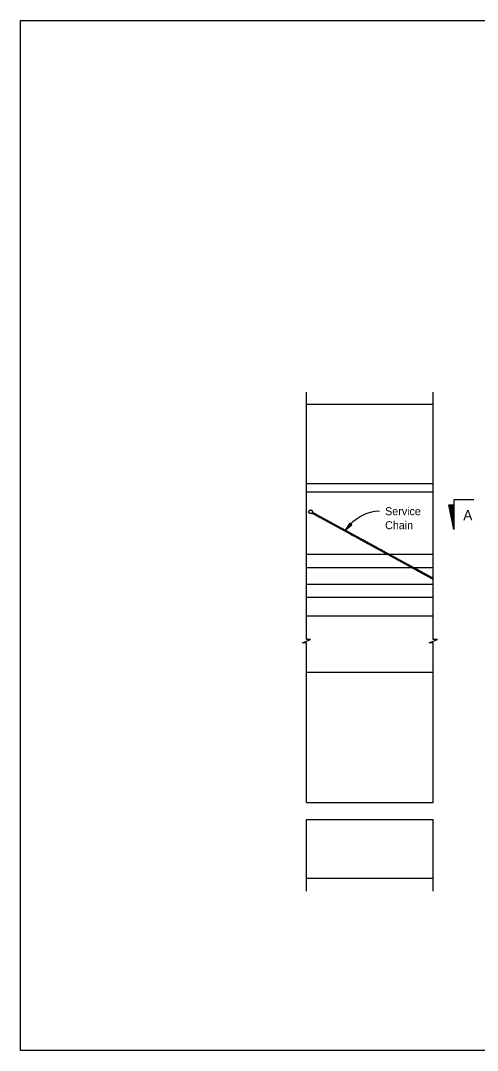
# Model space of a CAD drawing. Extents: x 83976.6 to 84012, y 72958.9 to 72975.6.
# Drawn here: x 83976.59 to 83982.35, y 72960.16 to 72973.13 of the extents above; entities that cross this region are included whole.
import ezdxf

# ---------------------------------------------------------------- set-up
doc = ezdxf.new("R2010")
doc.units = 0
for name, color, linetype in [('DSTitle', 7, 'Continuous'), ('Patterning', 7, 'Continuous'), ('PlotBorder_dp', 7, 'Continuous'), ('RefPtStaTie', 7, 'Continuous'), ('SheetLines_dp', 7, 'Continuous'), ('SupstrConc', 7, 'Continuous')]:
    doc.layers.add(name, color=color, linetype=linetype)

msp = doc.modelspace()

# ---------------------------------------------------------------- linework, layer by layer
at = {"layer": 'DSTitle'}
for radius in [0.0241, 0.0222]:
    msp.add_circle((83980.244, 72966.944), radius, dxfattribs=at)
for centre, major_axis, ratio in [((83980.274, 72966.926), (-0.0135, 0.0073), 0.530594), ((83980.274, 72966.926), (-0.0117, 0.0064), 0.458548), ((83980.298, 72966.914), (-0.0135, 0.0073), 0.530594), ((83980.298, 72966.914), (-0.0117, 0.0064), 0.458548), ((83980.321, 72966.901), (-0.0135, 0.0073), 0.530594), ((83980.321, 72966.901), (-0.0117, 0.0064), 0.458548), ((83980.344, 72966.888), (-0.0135, 0.0073), 0.530594), ((83980.344, 72966.888), (-0.0117, 0.0064), 0.458548), ((83980.368, 72966.875), (-0.0135, 0.0073), 0.530594), ((83980.368, 72966.875), (-0.0117, 0.0064), 0.458548), ((83980.391, 72966.863), (-0.0135, 0.0073), 0.530594), ((83980.391, 72966.863), (-0.0117, 0.0064), 0.458548), ((83980.414, 72966.85), (-0.0135, 0.0073), 0.530594), ((83980.414, 72966.85), (-0.0117, 0.0064), 0.458548), ((83980.438, 72966.837), (-0.0135, 0.0073), 0.530594), ((83980.438, 72966.837), (-0.0117, 0.0064), 0.458548), ((83980.461, 72966.825), (-0.0135, 0.0073), 0.530594), ((83980.461, 72966.825), (-0.0117, 0.0064), 0.458548), ((83980.484, 72966.812), (-0.0135, 0.0073), 0.530594), ((83980.484, 72966.812), (-0.0117, 0.0064), 0.458548), ((83980.508, 72966.799), (-0.0135, 0.0073), 0.530594), ((83980.508, 72966.799), (-0.0117, 0.0064), 0.458548), ((83980.531, 72966.786), (-0.0135, 0.0073), 0.530594), ((83980.531, 72966.786), (-0.0117, 0.0064), 0.458548), ((83980.554, 72966.774), (-0.0135, 0.0073), 0.530594), ((83980.554, 72966.774), (-0.0117, 0.0064), 0.458548), ((83980.578, 72966.761), (-0.0135, 0.0073), 0.530594), ((83980.578, 72966.761), (-0.0117, 0.0064), 0.458548), ((83980.601, 72966.748), (-0.0135, 0.0073), 0.530594), ((83980.601, 72966.748), (-0.0117, 0.0064), 0.458548), ((83980.624, 72966.735), (-0.0135, 0.0073), 0.530594), ((83980.624, 72966.735), (-0.0117, 0.0064), 0.458548), ((83980.648, 72966.723), (-0.0135, 0.0073), 0.530594), ((83980.648, 72966.723), (-0.0117, 0.0064), 0.458548), ((83980.671, 72966.71), (-0.0135, 0.0073), 0.530594), ((83980.671, 72966.71), (-0.0117, 0.0064), 0.458548), ((83980.694, 72966.697), (-0.0135, 0.0073), 0.530594), ((83980.694, 72966.697), (-0.0117, 0.0064), 0.458548), ((83980.718, 72966.685), (-0.0135, 0.0073), 0.530594), ((83980.718, 72966.685), (-0.0117, 0.0064), 0.458548), ((83980.741, 72966.672), (-0.0135, 0.0073), 0.530594), ((83980.741, 72966.672), (-0.0117, 0.0064), 0.458548), ((83980.764, 72966.659), (-0.0135, 0.0073), 0.530594), ((83980.764, 72966.659), (-0.0117, 0.0064), 0.458548), ((83980.788, 72966.646), (-0.0135, 0.0073), 0.530594), ((83980.788, 72966.646), (-0.0117, 0.0064), 0.458548), ((83980.811, 72966.634), (-0.0135, 0.0073), 0.530594), ((83980.811, 72966.634), (-0.0117, 0.0064), 0.458548), ((83980.834, 72966.621), (-0.0135, 0.0073), 0.530594), ((83980.834, 72966.621), (-0.0117, 0.0064), 0.458548), ((83980.857, 72966.608), (-0.0135, 0.0073), 0.530594), ((83980.857, 72966.608), (-0.0117, 0.0064), 0.458548), ((83980.881, 72966.596), (-0.0135, 0.0073), 0.530594), ((83980.881, 72966.596), (-0.0117, 0.0064), 0.458548), ((83980.904, 72966.583), (-0.0135, 0.0073), 0.530594), ((83980.904, 72966.583), (-0.0117, 0.0064), 0.458548), ((83980.927, 72966.57), (-0.0135, 0.0073), 0.530594), ((83980.927, 72966.57), (-0.0117, 0.0064), 0.458548), ((83980.951, 72966.557), (-0.0135, 0.0073), 0.530594), ((83980.951, 72966.557), (-0.0117, 0.0064), 0.458548), ((83980.974, 72966.545), (-0.0135, 0.0073), 0.530594), ((83980.974, 72966.545), (-0.0117, 0.0064), 0.458548), ((83980.997, 72966.532), (-0.0135, 0.0073), 0.530594), ((83980.997, 72966.532), (-0.0117, 0.0064), 0.458548), ((83981.021, 72966.519), (-0.0135, 0.0073), 0.530594), ((83981.021, 72966.519), (-0.0117, 0.0064), 0.458548), ((83981.044, 72966.507), (-0.0135, 0.0073), 0.530594), ((83981.044, 72966.507), (-0.0117, 0.0064), 0.458548), ((83981.067, 72966.494), (-0.0135, 0.0073), 0.530594), ((83981.067, 72966.494), (-0.0117, 0.0064), 0.458548), ((83981.091, 72966.481), (-0.0135, 0.0073), 0.530594), ((83981.091, 72966.481), (-0.0117, 0.0064), 0.458548), ((83981.114, 72966.468), (-0.0135, 0.0073), 0.530594), ((83981.114, 72966.468), (-0.0117, 0.0064), 0.458548), ((83981.137, 72966.456), (-0.0135, 0.0073), 0.530594), ((83981.137, 72966.456), (-0.0117, 0.0064), 0.458548), ((83981.161, 72966.443), (-0.0135, 0.0073), 0.530594), ((83981.161, 72966.443), (-0.0117, 0.0064), 0.458548), ((83981.184, 72966.43), (-0.0135, 0.0073), 0.530594), ((83981.184, 72966.43), (-0.0117, 0.0064), 0.458548), ((83981.207, 72966.417), (-0.0135, 0.0073), 0.530594), ((83981.207, 72966.417), (-0.0117, 0.0064), 0.458548), ((83981.231, 72966.405), (-0.0135, 0.0073), 0.530594), ((83981.231, 72966.405), (-0.0117, 0.0064), 0.458548), ((83981.254, 72966.392), (-0.0135, 0.0073), 0.530594), ((83981.254, 72966.392), (-0.0117, 0.0064), 0.458548), ((83981.277, 72966.379), (-0.0135, 0.0073), 0.530594), ((83981.277, 72966.379), (-0.0117, 0.0064), 0.458548), ((83981.301, 72966.367), (-0.0135, 0.0073), 0.530594), ((83981.301, 72966.367), (-0.0117, 0.0064), 0.458548), ((83981.324, 72966.354), (-0.0135, 0.0073), 0.530594), ((83981.324, 72966.354), (-0.0117, 0.0064), 0.458548), ((83981.347, 72966.341), (-0.0135, 0.0073), 0.530594), ((83981.347, 72966.341), (-0.0117, 0.0064), 0.458548), ((83981.371, 72966.328), (-0.0135, 0.0073), 0.530594), ((83981.371, 72966.328), (-0.0117, 0.0064), 0.458548), ((83981.394, 72966.316), (-0.0135, 0.0073), 0.530594), ((83981.394, 72966.316), (-0.0117, 0.0064), 0.458548), ((83981.417, 72966.303), (-0.0135, 0.0073), 0.530594), ((83981.417, 72966.303), (-0.0117, 0.0064), 0.458548), ((83981.441, 72966.29), (-0.0135, 0.0073), 0.530594), ((83981.441, 72966.29), (-0.0117, 0.0064), 0.458548), ((83981.464, 72966.278), (-0.0135, 0.0073), 0.530594), ((83981.464, 72966.278), (-0.0117, 0.0064), 0.458548), ((83981.487, 72966.265), (-0.0135, 0.0073), 0.530594), ((83981.487, 72966.265), (-0.0117, 0.0064), 0.458548), ((83981.511, 72966.252), (-0.0135, 0.0073), 0.530594), ((83981.511, 72966.252), (-0.0117, 0.0064), 0.458548), ((83981.534, 72966.239), (-0.0135, 0.0073), 0.530594), ((83981.534, 72966.239), (-0.0117, 0.0064), 0.458548), ((83981.557, 72966.227), (-0.0135, 0.0073), 0.530594), ((83981.557, 72966.227), (-0.0117, 0.0064), 0.458548), ((83981.581, 72966.214), (-0.0135, 0.0073), 0.530594), ((83981.581, 72966.214), (-0.0117, 0.0064), 0.458548), ((83981.604, 72966.201), (-0.0135, 0.0073), 0.530594), ((83981.604, 72966.201), (-0.0117, 0.0064), 0.458548), ((83981.627, 72966.188), (-0.0135, 0.0073), 0.530594), ((83981.627, 72966.188), (-0.0117, 0.0064), 0.458548), ((83981.65, 72966.176), (-0.0135, 0.0073), 0.530594), ((83981.65, 72966.176), (-0.0117, 0.0064), 0.458548), ((83981.674, 72966.163), (-0.0135, 0.0073), 0.530594), ((83981.674, 72966.163), (-0.0117, 0.0064), 0.458548), ((83981.697, 72966.15), (-0.0135, 0.0073), 0.530594), ((83981.697, 72966.15), (-0.0117, 0.0064), 0.458548), ((83981.72, 72966.138), (-0.0135, 0.0073), 0.530594), ((83981.72, 72966.138), (-0.0117, 0.0064), 0.458548), ((83981.744, 72966.125), (-0.0135, 0.0073), 0.530594), ((83981.744, 72966.125), (-0.0117, 0.0064), 0.458548), ((83981.767, 72966.112), (-0.0135, 0.0073), 0.530594), ((83981.767, 72966.112), (-0.0117, 0.0064), 0.458548)]:
    msp.add_ellipse(centre, major_axis=major_axis, ratio=ratio, dxfattribs=at)
for major_axis, ratio, start_param, end_param in [((-0.0135, 0.0073), 0.530594, 5.015995, 8.113767), ((-0.0117, 0.0064), 0.458548, 4.982983, 8.073526)]:
    msp.add_ellipse((83981.79, 72966.099), major_axis=major_axis, ratio=ratio, start_param=start_param, end_param=end_param, dxfattribs=at)
at = {"layer": 'PlotBorder_dp'}
for p, q in [((83981.79, 72966.405), (83980.191, 72966.405)), ((83981.79, 72966.238), (83980.191, 72966.238)), ((83981.79, 72966.03), (83980.191, 72966.03)), ((83981.79, 72965.863), (83980.191, 72965.863))]:
    msp.add_line(p, q, dxfattribs=at)
at = {"layer": 'RefPtStaTie'}
msp.add_lwpolyline([(83976.586, 72973.132), (83997.111, 72973.132), (83997.111, 72960.159), (83976.586, 72960.159)], close=True, dxfattribs=at)
at = {"layer": 'SheetLines_dp'}
for p, q in [((83981.994, 72967.032), (83982.049, 72966.72)), ((83982.049, 72966.72), (83982.001, 72967.033)), ((83982.049, 72966.72), (83982.01, 72967.032)), ((83982.049, 72966.72), (83982.019, 72967.032)), ((83982.049, 72966.72), (83982.029, 72967.033)), ((83982.049, 72966.72), (83982.039, 72967.033))]:
    msp.add_line(p, q, dxfattribs=at)
for points in [[(83980.191, 72963.281), (83980.191, 72965.292), (83980.139, 72965.292), (83980.191, 72965.315), (83980.243, 72965.337), (83980.191, 72965.337), (83980.191, 72968.453)], [(83981.79, 72963.281), (83981.79, 72965.292), (83981.738, 72965.292), (83981.79, 72965.315), (83981.842, 72965.337), (83981.79, 72965.337), (83981.79, 72968.453)], [(83982.3, 72967.095), (83982.049, 72967.095), (83982.049, 72966.72), (83981.987, 72967.033), (83982.049, 72967.033)], [(83980.191, 72963.281), (83981.79, 72963.281)], [(83980.191, 72962.167), (83980.191, 72963.068)], [(83980.191, 72963.068), (83981.79, 72963.068)], [(83981.79, 72962.167), (83981.79, 72963.068)]]:
    msp.add_lwpolyline(points, dxfattribs=at)
msp.add_lwpolyline([(83980.68, 72966.713), (83980.762, 72966.779), (83980.736, 72966.803)], close=True, dxfattribs=at)
msp.add_ellipse((83981.113, 72965.923), major_axis=(0.001, -1.03), ratio=0.654738, start_param=3.141603, end_param=3.837005, dxfattribs=at)
at = {"layer": 'SupstrConc'}
for p, q in [((83980.191, 72968.301), (83981.79, 72968.301)), ((83980.191, 72967.301), (83981.79, 72967.301)), ((83980.191, 72967.197), (83981.79, 72967.197)), ((83980.191, 72965.634), (83981.79, 72965.634)), ((83980.191, 72964.926), (83981.79, 72964.926)), ((83980.191, 72962.329), (83981.79, 72962.329))]:
    msp.add_line(p, q, dxfattribs=at)

# ---------------------------------------------------------------- texts
at = {"layer": 'Patterning'}
msp.add_text('A', height=0.128, dxfattribs=at).set_placement((83982.168, 72966.838))
at = {"layer": 'SheetLines_dp'}
for s, p in [('Service', (83981.183, 72966.901)), ('Chain', (83981.183, 72966.725))]:
    msp.add_text(s, height=0.1008, dxfattribs=at).set_placement(p)

doc.saveas('drawing.dxf')
